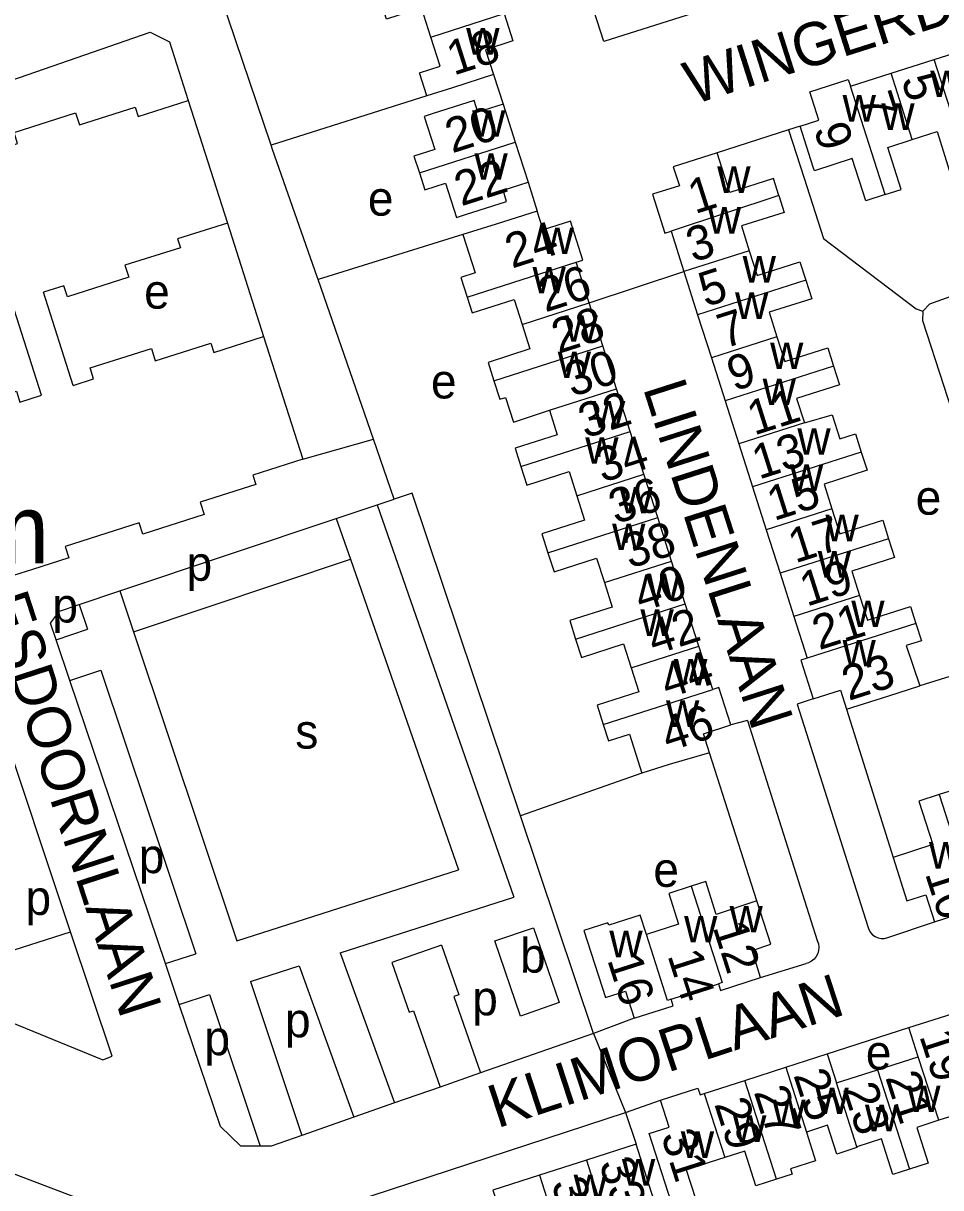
# Model space of a CAD drawing. Extents: x 159261 to 160849, y 382514 to 384534.
# Drawn here: x 160007.7 to 160114.3, y 383541.7 to 383676.9 of the extents above; entities that cross this region are included whole.
import ezdxf

# ---------------------------------------------------------------- set-up
doc = ezdxf.new("R2010")
doc.units = 0
for name, color, linetype in [('BLT_Basislijn', 7, 'Continuous'), ('BLT_Bebouwing', 7, 'Continuous'), ('BLT_Bebouwing_beschrifting', 7, 'Continuous'), ('BLT_Centroide', 7, 'Continuous'), ('BLT_Huisnummer', 7, 'Continuous'), ('BLT_Huisnummer_ tussenligend', 7, 'Continuous'), ('BLT_Onderverdeling_panden', 7, 'Continuous'), ('BLT_Straatnaam', 7, 'Continuous'), ('BLT_Vlakafsluiter', 7, 'Continuous')]:
    doc.layers.add(name, color=color, linetype=linetype)

msp = doc.modelspace()

# ---------------------------------------------------------------- linework, layer by layer
at = {"layer": 'BLT_Basislijn'}
for p, q in [((160036.53, 383662.7), (160028.64, 383686.01)), ((160062.37, 383670.9), (160063.47, 383667.47)), ((160054.61, 383668.42), (160036.53, 383662.7)), ((160096.62, 383664.47), (160088.33, 383661.81)), ((160097.98, 383664.91), (160096.62, 383664.47)), ((160066.37, 383658.4), (160067.43, 383655.04)), ((160031.45, 383653.66), (160035.66, 383640.48)), ((160058.81, 383652.32), (160041.99, 383647.12)), ((160048.41, 383628.56), (160041.99, 383647.12)), ((160040.23, 383626.24), (160048.41, 383628.56)), ((160050.82, 383621.62), (160048.41, 383628.56)), ((160044.09, 383619.36), (160048.83, 383620.95)), ((160048.83, 383620.95), (160050.82, 383621.62)), ((160048.83, 383620.95), (160064.72, 383575.37)), ((160018.97, 383610.95), (160044.09, 383619.36)), ((160044.09, 383619.36), (160045.74, 383614.63)), ((160020.56, 383606.19), (160045.74, 383614.63)), ((160045.74, 383614.63), (160058.31, 383578.57)), ((160014.23, 383609.36), (160018.97, 383610.95)), ((160018.97, 383610.95), (160020.56, 383606.19)), ((160014.23, 383609.36), (160015.19, 383606.5)), ((160011.56, 383605.28), (160010.9, 383607.22)), ((160011.56, 383605.28), (160015.19, 383606.5)), ((160020.56, 383606.19), (160032.55, 383570.33)), ((160013.16, 383600.55), (160011.56, 383605.28)), ((160013.16, 383600.55), (160016.77, 383601.76)), ((160024.26, 383567.68), (160013.16, 383600.55)), ((160016.77, 383601.76), (160027.79, 383568.81)), ((160099.48, 383598.42), (160097.64, 383597.81)), ((160097.64, 383597.81), (160105.84, 383571.98)), ((160103.38, 383597.22), (160108.78, 383580.01)), ((160091.85, 383595.9), (160089.91, 383595.38)), ((160091.85, 383595.9), (160099.96, 383570.35)), ((160092.96, 383574.98), (160087.46, 383592.16)), ((160079.6, 383589.79), (160065.5, 383584.82)), ((160073.98, 383559.57), (160065.5, 383584.82)), ((160032.55, 383570.33), (160058.31, 383578.57)), ((160044.56, 383568.92), (160064.72, 383575.37)), ((160004.58, 383568.6), (160013.22, 383571.37)), ((160056.34, 383569.81), (160050.55, 383567.79)), ((160056.34, 383569.81), (160058.35, 383564.06)), ((160024.26, 383567.68), (160027.79, 383568.81)), ((160044.56, 383568.92), (160050.87, 383551.49)), ((160025.86, 383562.94), (160024.26, 383567.68)), ((160034.14, 383565.59), (160039.79, 383567.4)), ((160039.79, 383567.4), (160046.15, 383549.85)), ((160050.55, 383567.79), (160052.56, 383562.03)), ((160093.39, 383566.06), (160098.67, 383567.68)), ((160034.14, 383565.59), (160040.11, 383547.73)), ((160025.86, 383562.94), (160029.37, 383564.07)), ((160029.37, 383564.07), (160035.25, 383546.49)), ((160058.35, 383564.06), (160057.77, 383563.85)), ((160057.77, 383563.85), (160060.87, 383554.99)), ((160052.56, 383562.03), (160053.05, 383562.2)), ((160053.05, 383562.2), (160056.15, 383553.34)), ((160078.69, 383561.33), (160073.98, 383559.57)), ((160101.12, 383557.18), (160110.61, 383560.24)), ((160073.98, 383559.57), (160060.87, 383554.99)), ((160060.87, 383554.99), (160056.15, 383553.34)), ((160056.15, 383553.34), (160050.87, 383551.49)), ((160077.68, 383550.38), (160081.75, 383551.8)), ((160050.87, 383551.49), (160046.15, 383549.85)), ((160046.15, 383549.85), (160040.11, 383547.73)), ((160077.68, 383550.38), (160078.92, 383546.71))]:
    msp.add_line(p, q, dxfattribs=at)
for points in [[(159984.92, 383655.64), (159990.19, 383664.65), (160022.48, 383675.81), (160024.72, 383674.71), (160026.89, 383667.91)], [(160096.62, 383664.47), (160098.45, 383658.86), (160100.69, 383651.85), (160111.47, 383643.72), (160112.24, 383643.44)], [(160041.99, 383647.12), (160041.88, 383647.43), (160036.69, 383662.22), (160036.53, 383662.7)], [(160112.24, 383643.44), (160113.04, 383644.27), (160123.79, 383648.14)], [(160112.24, 383643.44), (160112.2, 383642.33), (160124.37, 383604.79), (160124.21, 383603.76), (160111.87, 383599.91)], [(160065.5, 383584.82), (160052.92, 383622.29), (160050.82, 383621.62)], [(160010.9, 383607.22), (160011.96, 383608.6), (160014.23, 383609.36)], [(160013.22, 383571.37), (160004.63, 383597.06), (159994.83, 383593.86)], [(160105.84, 383571.98), (160105.95, 383571.63), (160106.14, 383571.3), (160106.39, 383571.03), (160106.7, 383570.81), (160107.04, 383570.67), (160107.41, 383570.6), (160107.79, 383570.6), (160108.15, 383570.69), (160113.59, 383572.53)], [(159935.34, 383566.83), (159950.74, 383571.9), (159950.72, 383570.15), (160006.11, 383549.4), (160004.08, 383544.22), (160019.68, 383538.31)], [(160018.05, 383556.91), (160013.22, 383571.37)], [(160099.96, 383570.35), (160100.1, 383569.98), (160100.15, 383569.6), (160100.13, 383569.21), (160100.03, 383568.84), (160099.85, 383568.49), (160099.61, 383568.19), (160099.31, 383567.95), (160098.97, 383567.77), (160098.67, 383567.68)], [(159997.07, 383559.15), (159998.99, 383563.84), (160016.98, 383556.49), (160018.05, 383556.91)], [(160035.25, 383546.49), (160033, 383546.49), (160030.64, 383548.77), (160025.86, 383562.94)], [(160051.3, 383497.97), (160017.51, 383505.98), (160023.43, 383526.72), (160026.52, 383531.81), (160027.8, 383533.09), (160030.02, 383534.48), (160034.57, 383536.26), (160077.68, 383550.38)], [(160040.11, 383547.73), (160036.55, 383546.49), (160035.25, 383546.49)]]:
    msp.add_lwpolyline(points, dxfattribs=at)
at = {"layer": 'BLT_Bebouwing'}
for p, q in [((160113.56, 383672.67), (160118.56, 383674.26)), ((160108.55, 383671.06), (160113.56, 383672.67)), ((160103.81, 383669.55), (160108.55, 383671.06)), ((160063.47, 383667.47), (160064.89, 383663.04)), ((160064.89, 383663.04), (160066.37, 383658.4)), ((160082.98, 383652.73), (160084.47, 383648.03)), ((160073.46, 383644.39), (160071.95, 383649.11)), ((160084.47, 383648.03), (160086.07, 383643.02)), ((160013.53, 383634.81), (160010.08, 383645.64)), ((160009.87, 383633.66), (160006.42, 383644.49)), ((160075.06, 383639.39), (160073.46, 383644.39)), ((160086.07, 383643.02), (160087.67, 383638.02)), ((160076.65, 383634.42), (160075.06, 383639.39)), ((160087.67, 383638.02), (160089.26, 383633.02)), ((160078.24, 383629.44), (160076.65, 383634.42)), ((160089.26, 383633.02), (160090.86, 383628.02)), ((160079.83, 383624.49), (160078.24, 383629.44)), ((160090.86, 383628.02), (160092.44, 383623.04)), ((160081.44, 383619.46), (160079.83, 383624.49)), ((160092.44, 383623.04), (160094.04, 383618.03)), ((160083.05, 383614.41), (160081.44, 383619.46)), ((160094.04, 383618.03), (160095.65, 383612.99)), ((160084.64, 383609.43), (160083.05, 383614.41)), ((160095.65, 383612.99), (160097.25, 383607.97)), ((160086.21, 383604.52), (160084.64, 383609.43)), ((160097.25, 383607.97), (160098.79, 383603.13)), ((160087.82, 383599.5), (160086.21, 383604.52)), ((160082.99, 383563.54), (160088.5, 383565.33)), ((160110.61, 383560.24), (160115.65, 383561.86)), ((160111.7, 383556.85), (160110.61, 383560.24)), ((160096.3, 383555.64), (160101.12, 383557.18)), ((160101.12, 383557.18), (160102.21, 383553.82)), ((160106.98, 383555.34), (160111.7, 383556.85)), ((160091.57, 383554.11), (160096.3, 383555.64)), ((160102.21, 383553.82), (160106.98, 383555.34)), ((160086.84, 383552.6), (160091.57, 383554.11)), ((160078.92, 383546.71), (160073.15, 383544.86)), ((160073.15, 383544.86), (160067.72, 383543.12))]:
    msp.add_line(p, q, dxfattribs=at)
for points in [[(160092.85, 383680.73), (160092.96, 383680.39), (160075.16, 383674.73), (160071.36, 383686.66)], [(160055.07, 383675.25), (160053.98, 383678.64), (160049.94, 383677.34), (160049.27, 383679.44)], [(160063.6, 383677.98), (160064.62, 383674.8), (160061.45, 383673.78), (160062.37, 383670.9)], [(160054.61, 383668.42), (160053.75, 383671.1), (160056.15, 383671.87), (160055.07, 383675.25)], [(160062.37, 383670.9), (160057.61, 383669.38), (160054.61, 383668.42)], [(160097.98, 383664.91), (160100.17, 383665.6), (160099.11, 383668.9), (160103.56, 383670.32), (160103.81, 383669.55)], [(159984.92, 383655.64), (159991.41, 383657.72), (159990.95, 383659.15), (159997.24, 383661.16), (159997.66, 383659.88), (160007.09, 383662.9), (160006.68, 383664.19), (160013.82, 383666.47), (160014.28, 383665.05), (160020.75, 383667.11), (160021.08, 383666.05), (160026.89, 383667.91)], [(160026.89, 383667.91), (160031.45, 383653.66)], [(160063.47, 383667.47), (160060.54, 383666.53), (160060.1, 383667.89), (160055.34, 383666.37), (160054.32, 383666.04), (160055.55, 383662.22), (160053.12, 383661.44), (160053.75, 383659.48)], [(160107.84, 383656.96), (160105.61, 383656.25), (160104.04, 383661.14), (160099.64, 383659.73), (160099.51, 383660.14), (160097.98, 383664.91)], [(160111.01, 383663.36), (160113.88, 383664.28), (160115.5, 383659.19), (160117.65, 383659.88)], [(160107.84, 383656.96), (160109.71, 383657.56), (160108.15, 383662.45), (160111.01, 383663.36)], [(160088.33, 383661.81), (160083.25, 383660.19), (160083.95, 383658), (160080.82, 383657), (160082.25, 383652.5), (160082.98, 383652.73)], [(160095.5, 383656.87), (160094.87, 383658.83), (160089.8, 383657.21), (160088.33, 383661.81)], [(160053.75, 383659.48), (160054.38, 383657.51), (160056.78, 383658.28), (160058.05, 383654.32), (160059.12, 383654.66), (160063.89, 383656.18), (160063.47, 383657.47), (160066.37, 383658.4)], [(160095.5, 383656.87), (160096.13, 383654.9), (160091.16, 383653.32), (160092.07, 383650.45)], [(160067.43, 383655.04), (160062.66, 383653.52), (160058.81, 383652.32)], [(160071.95, 383649.11), (160072.73, 383649.36), (160071.29, 383653.88), (160068.12, 383652.86), (160067.43, 383655.04)], [(160031.45, 383653.66), (160025.66, 383651.84), (160025.99, 383650.8), (160019.55, 383648.77), (160019.99, 383647.36), (160012.87, 383645.11), (160012.46, 383646.39), (160010.08, 383645.64)], [(160058.81, 383652.32), (160060.23, 383647.88), (160058.58, 383647.35), (160059.31, 383645.07)], [(160092.07, 383650.45), (160092.99, 383647.59), (160097.96, 383649.17), (160098.64, 383647.03)], [(160098.64, 383647.03), (160099.33, 383644.88), (160094.37, 383643.3), (160095.27, 383640.45)], [(160059.31, 383645.07), (160059.9, 383643.22), (160064.76, 383644.77), (160065.68, 383641.9)], [(160065.68, 383641.9), (160066.59, 383639.04), (160061.73, 383637.48), (160062.41, 383635.34)], [(159989.99, 383640.52), (159985, 383638.95), (159987.8, 383630.06), (159989.13, 383625.83), (159994.12, 383627.4), (159993.79, 383628.45), (160000.25, 383630.48), (159999.8, 383631.91), (160006.95, 383634.16), (160007.36, 383632.87), (160009.87, 383633.66)], [(160013.53, 383634.81), (160015.91, 383635.56), (160015.51, 383636.84), (160022.63, 383639.09), (160023.08, 383637.67), (160029.54, 383639.7), (160029.87, 383638.65), (160035.66, 383640.48)], [(160035.66, 383640.48), (160040.23, 383626.24)], [(160095.27, 383640.45), (160096.19, 383637.59), (160101.18, 383639.18), (160101.86, 383637.04)], [(160101.86, 383637.04), (160102.55, 383634.89), (160097.56, 383633.3), (160098.47, 383630.45)], [(160062.41, 383635.34), (160063.09, 383633.21), (160063.76, 383633.42), (160064.69, 383630.54), (160068.86, 383631.92)], [(160068.86, 383631.92), (160069.76, 383629.09), (160064.86, 383627.52), (160065.54, 383625.38)], [(160098.47, 383630.45), (160101.71, 383631.4), (160102.6, 383628.62), (160104.41, 383629.19), (160105.08, 383627.07)], [(160040.23, 383626.24), (160034.42, 383624.37), (160034.76, 383623.32), (160028.29, 383621.24), (160028.74, 383619.83), (160021.62, 383617.53), (160021.2, 383618.85), (160012.61, 383616.09), (160013.02, 383614.8), (160008.8, 383613.45)], [(160105.08, 383627.07), (160105.76, 383624.95), (160100.77, 383623.36), (160101.68, 383620.47)], [(160065.54, 383625.38), (160066.23, 383623.24), (160071.14, 383624.82), (160072.04, 383622)], [(160072.04, 383622), (160072.94, 383619.18), (160067.99, 383617.59), (160068.69, 383615.38)], [(160101.68, 383620.47), (160102.6, 383617.59), (160107.57, 383619.17), (160108.26, 383617.01)], [(160108.26, 383617.01), (160108.95, 383614.84), (160103.98, 383613.26), (160104.89, 383610.4)], [(160068.69, 383615.38), (160069.4, 383613.17), (160074.34, 383614.75), (160075.25, 383611.92)], [(160008.8, 383613.45), (160005.89, 383612.51), (160005.43, 383613.93), (159998.96, 383611.84), (159998.64, 383612.83), (159989.65, 383610.05), (159994.83, 383593.86)], [(160075.25, 383611.92), (160076.15, 383609.08), (160071.22, 383607.5), (160071.9, 383605.36)], [(160104.89, 383610.4), (160105.8, 383607.55), (160110.8, 383609.15), (160111.43, 383607.16)], [(160111.43, 383607.16), (160112.06, 383605.17), (160110.31, 383604.61), (160111.87, 383599.91)], [(160071.9, 383605.36), (160072.59, 383603.22), (160077.48, 383604.79), (160078.37, 383602.01)], [(160078.37, 383602.01), (160079.26, 383599.24), (160074.39, 383597.68), (160075.1, 383595.44)], [(160098.79, 383603.13), (160098.06, 383602.89), (160099.48, 383598.42)], [(160089.91, 383595.38), (160088.54, 383599.73), (160087.82, 383599.5)], [(160099.48, 383598.42), (160102.68, 383599.44), (160103.38, 383597.22)], [(160103.38, 383597.22), (160108.15, 383598.74), (160111.87, 383599.91)], [(160075.1, 383595.44), (160075.71, 383593.55), (160078.15, 383594.33), (160079.6, 383589.79)], [(160087.46, 383592.16), (160086.76, 383594.36), (160089.91, 383595.38)], [(160087.46, 383592.16), (160082.75, 383590.8), (160079.6, 383589.79)], [(160114.13, 383587.3), (160111.76, 383586.55), (160113.38, 383581.49), (160108.78, 383580.01)], [(160120.25, 383584.17), (160117.26, 383583.21), (160115.77, 383587.83), (160114.13, 383587.3)], [(160108.78, 383580.01), (160110.38, 383574.97), (160112.58, 383575.67), (160113.59, 383572.53)], [(160085.34, 383576.66), (160082.71, 383575.82), (160083.85, 383572.25), (160080.13, 383571.06)], [(160092.96, 383574.98), (160088.23, 383573.38), (160087.01, 383577.19), (160085.34, 383576.66)], [(160093.39, 383566.06), (160092.4, 383569.2), (160094.58, 383569.93), (160092.96, 383574.98)], [(160113.59, 383572.53), (160118.04, 383573.96), (160117.8, 383574.72), (160118.12, 383574.82)], [(160080.13, 383571.06), (160079.41, 383573.31), (160075.74, 383572.13), (160075.65, 383572.39), (160072.87, 383571.5), (160075.38, 383563.73), (160077.68, 383564.46), (160078.69, 383561.33)], [(160088.5, 383565.33), (160088.74, 383564.57), (160093.39, 383566.06)], [(160078.69, 383561.33), (160083.24, 383562.78), (160082.99, 383563.54)], [(160081.75, 383551.8), (160086.1, 383553.2), (160086.35, 383552.44), (160086.84, 383552.6)], [(160118.08, 383554.31), (160115.67, 383553.54), (160116.71, 383550.32), (160114.1, 383549.49)], [(160089.22, 383545.16), (160084.76, 383543.73), (160086.39, 383538.63), (160083.74, 383537.72), (160080.45, 383547.94), (160082.75, 383548.67), (160081.75, 383551.8)], [(160114.1, 383549.49), (160111.52, 383548.66), (160112.86, 383544.49), (160110.68, 383543.79)], [(160098.71, 383548.1), (160099.78, 383544.77), (160096.87, 383543.83), (160097.07, 383543.21), (160095.25, 383542.63)], [(160104.55, 383546.41), (160104.58, 383546.31), (160102.24, 383545.55), (160101.16, 383548.91), (160098.71, 383548.1)], [(160081.41, 383538.94), (160080.45, 383541.94), (160078.92, 383546.71)], [(160110.68, 383543.79), (160108.76, 383543.18), (160107.43, 383547.33), (160104.55, 383546.41)], [(160095.25, 383542.63), (160092.85, 383541.86), (160091.56, 383545.91), (160089.22, 383545.16)], [(160067.72, 383543.12), (160062.29, 383541.38), (160062.7, 383540.09)]]:
    msp.add_lwpolyline(points, dxfattribs=at)
msp.add_lwpolyline([(160062.53, 383570.3), (160067.02, 383571.84), (160069.99, 383563.14), (160065.49, 383561.58)], close=True, dxfattribs=at)
at = {"layer": 'BLT_Onderverdeling_panden'}
for p, q in [((160055.07, 383675.25), (160063.6, 383677.98)), ((160117.65, 383659.88), (160113.56, 383672.67)), ((160111.01, 383663.36), (160108.55, 383671.06)), ((160107.84, 383656.96), (160103.81, 383669.55)), ((160053.75, 383659.48), (160064.89, 383663.04)), ((160095.5, 383656.87), (160082.98, 383652.73)), ((160092.07, 383650.45), (160084.47, 383648.03)), ((160059.31, 383645.07), (160071.95, 383649.11)), ((160098.64, 383647.03), (160086.07, 383643.02)), ((160065.68, 383641.9), (160073.46, 383644.39)), ((160095.27, 383640.45), (160087.67, 383638.02)), ((160062.41, 383635.34), (160075.06, 383639.39)), ((160101.86, 383637.04), (160089.26, 383633.02)), ((160068.86, 383631.92), (160076.65, 383634.42)), ((160098.47, 383630.45), (160090.86, 383628.02)), ((160065.54, 383625.38), (160078.24, 383629.44)), ((160105.08, 383627.07), (160092.44, 383623.04)), ((160072.04, 383622), (160079.83, 383624.49)), ((160068.69, 383615.38), (160081.44, 383619.46)), ((160101.68, 383620.47), (160094.04, 383618.03)), ((160108.26, 383617.01), (160095.65, 383612.99)), ((160075.25, 383611.92), (160083.05, 383614.41)), ((160104.89, 383610.4), (160097.25, 383607.97)), ((160071.9, 383605.36), (160084.64, 383609.43)), ((160111.43, 383607.16), (160098.79, 383603.13)), ((160078.37, 383602.01), (160086.21, 383604.52)), ((160075.1, 383595.44), (160087.82, 383599.5)), ((160114.13, 383587.3), (160118.12, 383574.82)), ((160114.1, 383549.49), (160111.7, 383556.85)), ((160096.3, 383555.64), (160098.71, 383548.1)), ((160106.98, 383555.34), (160110.68, 383543.79)), ((160095.25, 383542.63), (160091.57, 383554.11)), ((160104.55, 383546.41), (160102.21, 383553.82)), ((160086.84, 383552.6), (160089.22, 383545.16)), ((160073.15, 383544.86), (160075.63, 383537.09)), ((160067.72, 383543.12), (160070.2, 383535.35))]:
    msp.add_line(p, q, dxfattribs=at)
for points in [[(160085.34, 383576.66), (160088.92, 383565.47), (160088.5, 383565.33)], [(160082.99, 383563.54), (160082.58, 383563.41), (160080.13, 383571.06)]]:
    msp.add_lwpolyline(points, dxfattribs=at)
at = {"layer": 'BLT_Vlakafsluiter'}
for p, q in [((160073.46, 383644.39), (160084.47, 383648.03)), ((160073.98, 383559.57), (160077.68, 383550.38))]:
    msp.add_line(p, q, dxfattribs=at)

# ---------------------------------------------------------------- texts
at = {"layer": 'BLT_Bebouwing_beschrifting'}
msp.add_text('Woonzorgcentrum', height=8, rotation=0.5505, dxfattribs=at).set_placement((159923.4, 383613.31))
at = {"layer": 'BLT_Centroide'}
for s, p in [('w', (160059.19, 383673.22)), ('w', (160113.09, 383668.28)), ('w', (160102.91, 383665.44)), ('w', (160059.88, 383663.69)), ('w', (160107.41, 383664.48)), ('w', (160060.15, 383658.69)), ('w', (160088.35, 383657.16)), ('e', (160047.77, 383654.52)), ('w', (160087.25, 383652.44)), ('w', (160067.84, 383650.06)), ('w', (160091.3, 383646.75)), ('w', (160066.89, 383645.5)), ('e', (160021.78, 383643.72)), ('w', (160090.42, 383642.53)), ('w', (160070.62, 383639.88)), ('w', (160094.49, 383636.72)), ('w', (160069.82, 383635.66)), ('e', (160055.1, 383633.3)), ('w', (160093.62, 383632.53)), ('w', (160073.8, 383629.91)), ('w', (160097.66, 383626.75)), ('w', (160073.02, 383625.72)), ('w', (160096.8, 383622.56)), ('w', (160076.99, 383619.94)), ('e', (160111.4, 383619.8)), ('w', (160100.92, 383616.72)), ('w', (160076.14, 383615.69)), ('w', (160100.02, 383612.5)), ('p', (160026.71, 383612.13)), ('w', (160080.2, 383609.88)), ('p', (160011.12, 383607.28)), ('w', (160079.43, 383605.72)), ('w', (160103.92, 383606.75)), ('w', (160102.9, 383602.19)), ('w', (160083.34, 383599.97)), ('w', (160082.4, 383595.16)), ('s', (160039.34, 383592.64)), ('w', (160112.95, 383578.71)), ('p', (160021.16, 383578.18)), ('e', (160080.93, 383576.59)), ('p', (160008, 383573.33)), ('w', (160089.78, 383571.31)), ('w', (160084.5, 383570.14)), ('b', (160065.45, 383566.63)), ('w', (160075.82, 383568.41)), ('p', (160059.89, 383561.67)), ('p', (160038.14, 383559.12)), ('p', (160028.78, 383557.04)), ('e', (160105.61, 383555.37)), ('w', (160099.76, 383550.2)), ('w', (160110.42, 383550.44)), ('w', (160094.75, 383548.81)), ('w', (160105.51, 383548.21)), ('w', (160090.19, 383546.97)), ('w', (160084.12, 383545.12)), ('w', (160077.28, 383541.91)), ('w', (160071.67, 383540.09))]:
    msp.add_text(s, height=4, dxfattribs=at).set_placement(p)
at = {"layer": 'BLT_Huisnummer'}
for s, rotation, p in [('5', 287.7329, (160109.7, 383670.34)), ('20', 17.7464, (160057.55, 383661.74)), ('9', 287.7355, (160099.53, 383664.62)), ('22', 17.7496, (160058.61, 383655.59)), ('1', 17.6878, (160085.75, 383654.68)), ('26', 17.7393, (160068.37, 383643.27)), ('5', 17.7008, (160086.98, 383643.89)), ('30', 17.7495, (160071.47, 383633.44)), ('9', 17.6907, (160090.29, 383634.11)), ('34', 17.7412, (160075.01, 383623.49)), ('13', 17.6874, (160093.19, 383623.86)), ('17', 17.6938, (160097.4, 383614.13)), ('38', 17.7495, (160078.18, 383613.51)), ('42', 17.7441, (160081.02, 383603.48)), ('21', 17.6782, (160100.18, 383604.05)), ('23', 17.6849, (160103.61, 383598.17)), ('46', 17.7464, (160082.64, 383592.25)), ('10', 287.7476, (160112.46, 383578.14)), ('12', 287.7317, (160087.8, 383571.92)), ('16', 287.7429, (160075.55, 383568.13)), ('25', 287.9638, (160097.18, 383554.74)), ('21', 287.953, (160107.85, 383554.47)), ('31', 287.7637, (160081.79, 383547.73)), ('33', 287.7637, (160074.6, 383544.49))]:
    msp.add_text(s, height=4, rotation=rotation, dxfattribs=at).set_placement(p)
at = {"layer": 'BLT_Huisnummer_ tussenligend'}
for s, rotation, p in [('18', 17.7509, (160057.73, 383670.77)), ('7', 287.7329, (160104.66, 383668.17)), ('24', 17.7496, (160064.5, 383648.36)), ('3', 17.6878, (160085.54, 383649.07)), ('28', 17.7393, (160069.91, 383638.46)), ('7', 17.7008, (160089.16, 383639.07)), ('32', 17.7495, (160073.01, 383628.63)), ('11', 17.6907, (160092.63, 383628.98)), ('36', 17.7412, (160076.54, 383618.68)), ('15', 17.6874, (160094.94, 383619.05)), ('19', 17.6938, (160098.73, 383609.1)), ('40', 17.7495, (160079.48, 383608.48)), ('44', 17.7441, (160082.54, 383598.44)), ('14', 287.7317, (160082.54, 383568.63)), ('19', 287.9486, (160111.8, 383559.28)), ('27', 287.9638, (160092.58, 383552.78)), ('23', 287.953, (160102.9, 383553.15)), ('29', 287.9638, (160087.98, 383551.38)), ('35', 287.7637, (160069.04, 383542.17))]:
    msp.add_text(s, height=4, rotation=rotation, dxfattribs=at).set_placement(p)
at = {"layer": 'BLT_Straatnaam'}
for s, rotation, p in [('WINGERDLAAN', 17.6442, (160085.52, 383667.37)), ('LINDENLAAN', 287.741, (160079.7, 383634.51)), ('ESDOORNLAAN', 287.9748, (160003.33, 383609.89)), ('KLIMOPLAAN', 18.1414, (160062.8, 383548.53))]:
    msp.add_text(s, height=5, rotation=rotation, dxfattribs=at).set_placement(p)

doc.saveas('drawing.dxf')
